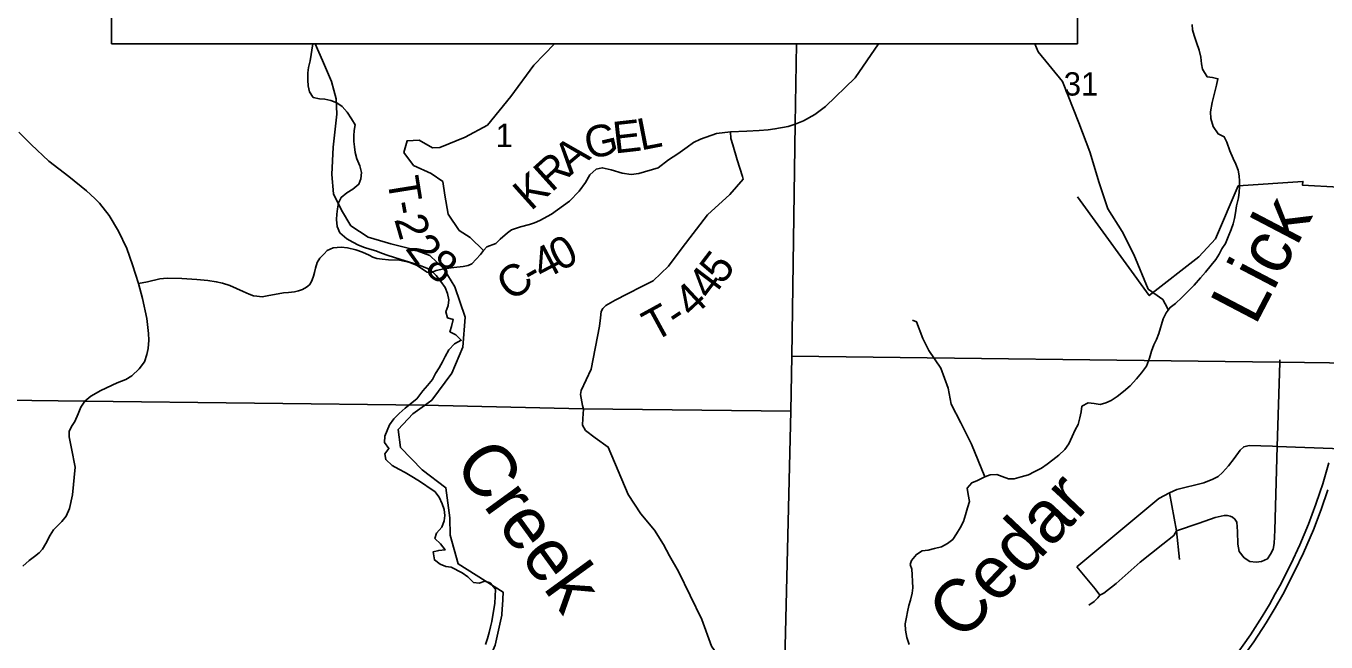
# Model space of a CAD drawing. Extents: x 0 to 34, y 0 to 22.
# Drawn here: x 3.211 to 5.55, y 15.265 to 16.371 of the extents above; entities that cross this region are included whole.
import ezdxf

# ---------------------------------------------------------------- set-up
doc = ezdxf.new("R2010")
doc.units = 0
for name, color, linetype in [('GM_X_Corporation', 7, 'Continuous'), ('GM_X_County_Road', 7, 'Continuous'), ('GM_X_County_Road_Text', 7, 'Continuous'), ('GM_X_Minor_River', 7, 'Continuous'), ('GM_X_Minor_River_Text', 7, 'Continuous'), ('GM_X_Section_Text', 7, 'Continuous'), ('GM_X_State_Route', 7, 'Continuous'), ('GM_X_Township_Road', 7, 'Continuous'), ('GM_X_Township_Road_Text', 7, 'Continuous'), ('GM_X_US_Route', 7, 'Continuous'), ('SH_Text', 7, 'Continuous')]:
    doc.layers.add(name, color=color, linetype=linetype)

msp = doc.modelspace()

# ---------------------------------------------------------------- linework, layer by layer
at = {"layer": 'GM_X_Corporation'}
for points in [[(4.5973, 16.3396), (4.5948, 16.1954), (4.5888, 15.778), (5.4664, 15.7674), (5.6014, 15.7658)], [(5.6386, 16.0784), (5.5079, 16.0853), (5.5084, 16.0923), (5.3919, 16.0842), (5.3514, 15.9891), (5.3213, 15.9569), (5.2318, 15.887), (5.1027, 16.0647)], [(5.6014, 15.7658), (5.4664, 15.7674), (4.5888, 15.778), (4.5873, 15.6794), (4.5738, 15.1325), (4.5685, 14.9157), (4.5617, 14.6817), (4.5616, 14.6767), (4.5614, 14.6695), (4.5505, 14.2449), (4.5507, 14.1138), (4.5503, 14.1), (8.9, 14.1)]]:
    msp.add_lwpolyline(points, dxfattribs=at)
msp.add_lwpolyline([(2.1, 15.7148), (2.1, 14.1), (4.5503, 14.1), (4.5507, 14.1138), (4.5505, 14.2449), (4.5614, 14.6695), (4.5616, 14.6767), (4.5617, 14.6817), (4.5685, 14.9157), (4.5738, 15.1325), (4.5873, 15.6794), (4.2138, 15.6834), (3.9277, 15.6898), (3.3171, 15.6975), (2.4078, 15.7088)], close=True, dxfattribs=at)
at = {"layer": 'GM_X_County_Road'}
for points in [[(4.5465, 16.1848), (4.5584, 16.1867), (4.5821, 16.1911), (4.595, 16.1948), (4.6099, 16.2009), (4.6301, 16.2122), (4.6497, 16.2271), (4.7026, 16.2782), (4.7447, 16.3396)], [(3.4137, 15.9087), (3.4296, 15.9117), (3.4519, 15.9171), (3.4649, 15.9181), (3.4916, 15.9178), (3.5186, 15.9158), (3.5386, 15.9141), (3.5536, 15.912), (3.5646, 15.9093), (3.5778, 15.9052), (3.59, 15.8998), (3.6016, 15.8944), (3.6124, 15.8897), (3.6204, 15.8863), (3.6262, 15.8857), (3.636, 15.885), (3.645, 15.8864), (3.6746, 15.8917), (3.6833, 15.8926), (3.6942, 15.8936), (3.7013, 15.8954), (3.7085, 15.8981), (3.7158, 15.9021), (3.721, 15.9066), (3.7244, 15.9114), (3.7262, 15.9155), (3.7287, 15.9219), (3.7303, 15.9286), (3.7318, 15.9363), (3.7349, 15.9464), (3.7401, 15.9542), (3.7478, 15.9623), (3.7531, 15.968), (3.7641, 15.9731), (3.7782, 15.9743), (3.7896, 15.9727), (3.8043, 15.9693), (3.8163, 15.9653), (3.8283, 15.9596), (3.835, 15.9558), (3.8426, 15.9536), (3.8522, 15.9523), (3.8635, 15.9514), (3.8831, 15.9509), (3.8999, 15.9471), (3.9136, 15.9417), (3.933, 15.9289), (3.9396, 15.928), (3.949, 15.9323), (3.9631, 15.9349), (3.9811, 15.9375), (3.9975, 15.9394), (4.0067, 15.9408), (4.0134, 15.9438), (4.0287, 15.9607), (4.0341, 15.9681), (4.04, 15.9745), (4.0562, 15.9809), (4.0644, 15.9883), (4.0774, 15.9999), (4.0848, 16.005), (4.101, 16.0107), (4.1172, 16.0148), (4.1263, 16.0177), (4.1357, 16.0217), (4.1563, 16.0335), (4.1891, 16.0567), (4.2061, 16.0745), (4.2179, 16.0905), (4.2255, 16.1043), (4.237, 16.1143), (4.248, 16.1169), (4.2637, 16.1132), (4.2836, 16.1072), (4.2998, 16.1049), (4.3137, 16.1062), (4.3486, 16.1166), (4.3673, 16.1307), (4.3836, 16.1418), (4.4005, 16.1538), (4.4122, 16.1622), (4.4245, 16.1679), (4.4532, 16.1781), (4.4788, 16.1813), (4.5082, 16.1826), (4.5299, 16.1838), (4.5465, 16.1848)]]:
    msp.add_lwpolyline(points, dxfattribs=at)
at = {"layer": 'GM_X_Minor_River'}
for points in [[(5.3245, 16.3158), (5.3219, 16.3278), (5.3169, 16.3417), (5.3127, 16.3542), (5.31, 16.3647), (5.3094, 16.3742)], [(3.7272, 16.3396), (3.7223, 16.309), (3.7194, 16.2968), (3.7184, 16.2873), (3.7182, 16.2744), (3.7191, 16.2641), (3.7212, 16.2531), (3.7281, 16.2433), (3.7392, 16.2408), (3.7491, 16.2398), (3.7598, 16.2377), (3.7705, 16.2336), (3.7801, 16.2269), (3.789, 16.2164), (3.7968, 16.2044), (3.8034, 16.1938), (3.8016, 16.1839), (3.801, 16.174), (3.8011, 16.1637), (3.802, 16.1542), (3.8033, 16.144), (3.8065, 16.1326), (3.8116, 16.1202), (3.8148, 16.1084), (3.8134, 16.0966), (3.8098, 16.0871), (3.7989, 16.0782), (3.7883, 16.0716), (3.7781, 16.0634), (3.7733, 16.0539), (3.7716, 16.0428)], [(5.2659, 15.8612), (5.2648, 15.8643), (5.2566, 15.8798), (5.2298, 15.8987), (5.2045, 15.9606), (5.1833, 16.0024), (5.1577, 16.0427), (5.1421, 16.0899), (5.1249, 16.1451), (5.105, 16.1972), (5.0761, 16.272), (5.032, 16.3248), (5.0263, 16.3396)], [(4.8018, 15.4037), (4.804, 15.4108), (4.8131, 15.4218), (4.8232, 15.4282), (4.8342, 15.4296), (4.8459, 15.4327), (4.8583, 15.4357), (4.8688, 15.4414), (4.8784, 15.4489), (4.885, 15.459), (4.8915, 15.4695), (4.8976, 15.4811), (4.9014, 15.493), (4.9052, 15.5056), (4.9086, 15.5172), (4.9063, 15.5296), (4.9041, 15.541), (4.9125, 15.5507), (4.923, 15.5549), (4.9361, 15.561), (4.9459, 15.5651), (4.958, 15.5655), (4.9676, 15.562), (4.9788, 15.5578), (4.9887, 15.5577), (5.0015, 15.5611), (5.0147, 15.565), (5.0252, 15.5703), (5.0379, 15.5771), (5.0483, 15.5839), (5.0587, 15.5918), (5.0691, 15.6002), (5.0802, 15.6104), (5.0875, 15.6205), (5.0935, 15.634), (5.0988, 15.6456), (5.1039, 15.6556), (5.1073, 15.6671), (5.1096, 15.6782), (5.1104, 15.6881), (5.122, 15.6942), (5.1331, 15.693), (5.1438, 15.6911), (5.154, 15.6945), (5.1637, 15.6986), (5.1741, 15.7054), (5.1856, 15.7148), (5.1975, 15.7247), (5.2093, 15.7373), (5.218, 15.7482), (5.2272, 15.7603), (5.2324, 15.7745), (5.2358, 15.7871), (5.2404, 15.7983), (5.245, 15.8083), (5.2489, 15.8187), (5.2568, 15.8452), (5.2622, 15.856), (5.2695, 15.8658), (5.2791, 15.8729), (5.2906, 15.8835), (5.3016, 15.8945), (5.3127, 15.9059), (5.3244, 15.9192), (5.3329, 15.929), (5.3435, 15.9415), (5.3515, 15.9516), (5.3577, 15.9613), (5.3627, 15.971), (5.3689, 15.9807), (5.3742, 15.9926), (5.3795, 16.0057), (5.383, 16.0157), (5.3853, 16.0257), (5.3873, 16.0356), (5.3892, 16.0482), (5.3925, 16.0628), (5.3937, 16.0727), (5.3942, 16.0826), (5.3943, 16.0925), (5.3936, 16.1024), (5.3917, 16.1122), (5.388, 16.1231), (5.3831, 16.1336), (5.377, 16.1471), (5.3715, 16.1629), (5.367, 16.1726), (5.3558, 16.1776), (5.3467, 16.191), (5.3428, 16.2053), (5.3424, 16.2175), (5.3449, 16.2343), (5.3494, 16.2511), (5.3531, 16.2649), (5.3554, 16.2768), (5.3458, 16.2788), (5.3363, 16.28), (5.3275, 16.2938), (5.326, 16.3036), (5.3245, 16.3158)], [(3.7716, 16.0428), (3.7705, 16.0333), (3.7699, 16.0238), (3.7712, 16.0113), (3.7759, 15.9999), (3.7883, 15.9891), (3.7994, 15.9828), (3.8093, 15.9776), (3.8201, 15.9732), (3.8296, 15.9706), (3.8403, 15.9677), (3.8506, 15.9633), (3.8625, 15.9593), (3.8724, 15.956), (3.8858, 15.9517), (3.9072, 15.9451), (3.9183, 15.9415), (3.9294, 15.9374), (3.9389, 15.9334), (3.949, 15.9233), (3.9575, 15.9124), (3.9652, 15.9014), (3.9696, 15.8909), (3.9716, 15.8795), (3.9706, 15.8692), (3.9662, 15.8577), (3.9694, 15.8471), (3.9797, 15.8439), (3.9764, 15.8316), (3.9739, 15.8221), (3.9846, 15.8162), (3.9943, 15.8068), (3.9822, 15.8002), (3.9721, 15.7898), (3.9654, 15.7775), (3.9606, 15.7679), (3.9546, 15.7572), (3.9479, 15.7472), (3.9427, 15.7361), (3.9337, 15.7257), (3.9251, 15.7161), (3.9143, 15.7015), (3.903, 15.6922), (3.8932, 15.6849), (3.8823, 15.6752), (3.8729, 15.6656), (3.8651, 15.6545), (3.861, 15.6445), (3.8566, 15.6342), (3.8564, 15.6232), (3.8641, 15.6123), (3.857, 15.6027), (3.8583, 15.5924), (3.8698, 15.5815), (3.8821, 15.5749), (3.8932, 15.5689), (3.9051, 15.5619), (3.9159, 15.5556), (3.9266, 15.5489), (3.9366, 15.5418), (3.9466, 15.5351), (3.9547, 15.5249), (3.9598, 15.5129), (3.9634, 15.5023), (3.9647, 15.492), (3.9637, 15.4821), (3.9592, 15.471), (3.9495, 15.4602), (3.947, 15.4507), (3.957, 15.441), (3.9651, 15.4301), (3.9537, 15.4291), (3.9439, 15.4267), (3.946, 15.4119), (3.9563, 15.4041), (3.9663, 15.4004), (3.9762, 15.3987), (3.996, 15.3887)], [(4.9361, 15.561), (4.912, 15.6198), (4.8928, 15.6586), (4.8755, 15.6921), (4.8701, 15.7205), (4.857, 15.7568), (4.8352, 15.7884), (4.8247, 15.8098), (4.8135, 15.8397), (4.8063, 15.843)], [(4.8018, 15.4037), (4.8047, 15.3953), (4.8056, 15.3854), (4.8059, 15.3733), (4.8065, 15.3619), (4.8052, 15.352), (4.8024, 15.3397), (4.7992, 15.3298), (4.7971, 15.3187), (4.7954, 15.3092), (4.7926, 15.297), (4.7932, 15.2859), (4.7958, 15.2723), (4.8002, 15.2598)], [(3.996, 15.3887), (4.0058, 15.3813), (4.0162, 15.3715), (4.0264, 15.3704), (4.0367, 15.3735), (4.0462, 15.3706), (4.0558, 15.3596), (4.0555, 15.346), (4.0545, 15.3342), (4.0527, 15.3228), (4.0512, 15.3129), (4.0491, 15.3011), (4.0469, 15.2915), (4.0447, 15.2817), (4.0417, 15.2706), (4.038, 15.2599)]]:
    msp.add_lwpolyline(points, dxfattribs=at)
at = {"layer": 'GM_X_State_Route'}
for points in [[(3.4137, 15.9087), (3.403, 15.9423), (3.3924, 15.9718), (3.3774, 16.0029), (3.3607, 16.0307), (3.3437, 16.0533), (3.3351, 16.0618), (3.3199, 16.0751), (3.288, 16.1009), (3.2525, 16.1288), (3.2208, 16.1586), (3.1981, 16.1808)], [(3.2057, 15.4009), (3.2169, 15.4107), (3.2265, 15.4179), (3.2346, 15.4249), (3.2406, 15.4311), (3.2471, 15.4412), (3.2544, 15.4566), (3.2609, 15.4658), (3.2759, 15.4808), (3.2833, 15.4906), (3.2896, 15.5044), (3.2948, 15.5287), (3.2999, 15.5784), (3.2931, 15.6122), (3.289, 15.6329), (3.289, 15.6429), (3.2928, 15.6518), (3.2988, 15.661), (3.3051, 15.6744), (3.3097, 15.6865), (3.3173, 15.697), (3.3279, 15.7061), (3.3458, 15.7166), (3.3752, 15.73), (3.3906, 15.7361), (3.4016, 15.7431), (3.415, 15.7553), (3.4241, 15.7682), (3.4287, 15.7809), (3.431, 15.7918), (3.4319, 15.8067), (3.4313, 15.819), (3.4287, 15.846), (3.4209, 15.8818), (3.4137, 15.9087)]]:
    msp.add_lwpolyline(points, dxfattribs=at)
at = {"layer": 'GM_X_Township_Road'}
for points in [[(3.9631, 15.9349), (3.938, 15.9593), (3.9082, 15.9701), (3.8678, 15.9798), (3.827, 15.9918), (3.7958, 16.0124), (3.7789, 16.0404), (3.7642, 16.0701), (3.7612, 16.1045), (3.764, 16.1539), (3.7703, 16.2128), (3.7693, 16.2405), (3.7611, 16.2718), (3.7447, 16.3098), (3.7315, 16.3396)], [(3.9646, 16.0674), (3.9609, 16.092), (3.9403, 16.1062), (3.9086, 16.121), (3.891, 16.1439), (3.8968, 16.1652), (3.9188, 16.1662), (3.9428, 16.1525), (3.9557, 16.1534), (4.001, 16.1717), (4.0413, 16.193), (4.0836, 16.2447), (4.1246, 16.3013), (4.162, 16.3396)], [(4.2126, 15.6897), (4.2089, 15.7091), (4.2099, 15.7167), (4.2282, 15.7546), (4.2431, 15.8318), (4.2448, 15.847), (4.246, 15.8583), (4.2489, 15.864), (4.2544, 15.8695), (4.271, 15.879), (4.2936, 15.8901), (4.319, 15.9035), (4.3393, 15.9138), (4.3673, 15.9398), (4.3915, 15.973), (4.4372, 16.0324), (4.4772, 16.0685), (4.5015, 16.0962), (4.5, 16.1013), (4.4907, 16.1308), (4.4827, 16.1577), (4.479, 16.1695), (4.4788, 16.1813)], [(4.0341, 15.9681), (4.0105, 15.9916), (3.9907, 16.0039), (3.9705, 16.0332), (3.9646, 16.0674)], [(4.0681, 15.3252), (4.0683, 15.3294), (4.0694, 15.3542), (3.9885, 15.4047), (3.9742, 15.4564), (3.9735, 15.4879), (3.9667, 15.5416), (3.9239, 15.574), (3.8847, 15.6141), (3.8806, 15.6463), (3.9073, 15.6745), (3.9279, 15.6892), (3.9413, 15.6988), (3.977, 15.7478), (3.9969, 15.7945), (4.0014, 15.8484), (3.9828, 15.9026), (3.9631, 15.9349)], [(5.1232, 15.3304), (5.1328, 15.3374), (5.1396, 15.3441), (5.1433, 15.3488), (5.1503, 15.3522), (5.1722, 15.3699), (5.2159, 15.4079), (5.2566, 15.4402), (5.2764, 15.4559), (5.2807, 15.4643), (5.3215, 15.4779), (5.3505, 15.4881), (5.3666, 15.4918), (5.3727, 15.4919), (5.3773, 15.4907), (5.3819, 15.4889), (5.3861, 15.4853), (5.3896, 15.4799), (5.3908, 15.4632), (5.3914, 15.4403), (5.3937, 15.427), (5.4028, 15.4159), (5.4129, 15.4093), (5.4242, 15.408), (5.4341, 15.4089), (5.4444, 15.4142), (5.4501, 15.4224), (5.4547, 15.4313), (5.4567, 15.4414), (5.4576, 15.4657), (5.4622, 15.6159), (5.4666, 15.7669), (5.4667, 15.7714)], [(4.5502, 15.1611), (4.5496, 15.1619), (4.4934, 15.1962), (4.4711, 15.219), (4.4444, 15.2572), (4.4269, 15.3047), (4.385, 15.3914), (4.3689, 15.4195), (4.3582, 15.4397), (4.3417, 15.4652), (4.3172, 15.495), (4.2948, 15.5298), (4.2586, 15.6149), (4.235, 15.6314), (4.2175, 15.6447), (4.2125, 15.6544), (4.2131, 15.6659), (4.214, 15.6829), (4.2126, 15.6897)], [(5.1019, 15.3994), (5.2489, 15.5226), (5.2684, 15.5327), (5.2816, 15.5388), (5.3304, 15.5508), (5.3465, 15.557), (5.3562, 15.562), (5.364, 15.5688), (5.3747, 15.5809), (5.3846, 15.5943), (5.3955, 15.6095), (5.402, 15.6155), (5.4118, 15.6178), (5.4535, 15.6162)], [(5.4535, 15.6162), (5.4622, 15.6159), (5.5619, 15.6123), (5.5742, 15.6117), (5.6094, 15.6105)], [(5.2865, 15.4125), (5.2807, 15.4643), (5.2684, 15.5327)], [(5.1433, 15.3488), (5.1344, 15.3601), (5.1104, 15.3885), (5.1019, 15.3994)], [(4.1181, 15.1541), (4.112, 15.1562), (4.0597, 15.1614), (4.038, 15.2179), (4.0551, 15.2588), (4.0675, 15.3128), (4.0681, 15.3252)]]:
    msp.add_lwpolyline(points, dxfattribs=at)
at = {"layer": 'GM_X_US_Route'}
for points in [[(5.388, 15.2404), (5.4139, 15.2775), (5.4349, 15.3101), (5.448, 15.332), (5.4587, 15.3508), (5.4666, 15.3654), (5.4866, 15.4046), (5.5026, 15.4393), (5.5182, 15.4762), (5.5317, 15.5124), (5.5389, 15.5331), (5.544, 15.5488), (5.5553, 15.5862)], [(5.389, 15.2214), (5.4201, 15.265), (5.4421, 15.2992), (5.4584, 15.3258), (5.472, 15.35), (5.4934, 15.3911), (5.5092, 15.4249), (5.5273, 15.4662), (5.541, 15.5026), (5.5533, 15.5378)]]:
    msp.add_lwpolyline(points, dxfattribs=at)
at = {"layer": 'SH_Text'}
msp.add_lwpolyline([(3.3651, 16.3396), (5.1027, 16.3396), (5.1027, 17.0396), (3.3651, 17.0396)], close=True, dxfattribs=at)

# ---------------------------------------------------------------- texts
at = {"layer": 'GM_X_County_Road_Text'}
for s, rotation, p in [('G', 12.8797, (4.223, 16.1313)), ('E', 6.4377, (4.2701, 16.1422)), ('L', 10.9737, (4.3172, 16.1477)), ('A', 40.1232, (4.1911, 16.1023)), ('R', 41.9739, (4.1568, 16.0714)), ('K', 41.9823, (4.1196, 16.0379)), ('4', 27.752, (4.1405, 15.9132)), ('0', 27.8832, (4.1716, 15.9296)), ('C', 36.9035, (4.0849, 15.875)), ('-', 29.3799, (4.1206, 15.902))]:
    msp.add_text(s, height=0.0568, rotation=rotation, dxfattribs=at).set_placement(p)
at = {"layer": 'GM_X_Minor_River_Text'}
for s, height, rotation, p in [('Lick', 0.09467, 62.401, (5.4225, 15.8311)), ('Creek', 0.09468, 305.9828, (3.9791, 15.5837)), ('Cedar', 0.09468, 46.5505, (4.8944, 15.2633))]:
    msp.add_text(s, height=height, rotation=rotation, dxfattribs=at).set_placement(p)
at = {"layer": 'GM_X_Section_Text'}
for s, height, p in [('31', 0.04186, (5.0781, 16.2465)), ('1', 0.0419, (4.056, 16.154))]:
    msp.add_text(s, height=height, rotation=0, dxfattribs=at).set_placement(p)
at = {"layer": 'GM_X_Township_Road_Text'}
for s, rotation, p in [('T', 279.1023, (3.8607, 16.0968)), ('-', 280.4116, (3.8676, 16.0535)), ('2', 286.2071, (3.8733, 16.0244)), ('2', 305.8587, (3.8923, 15.9718)), ('8', 323.1255, (3.9259, 15.9302)), ('5', 52.7065, (4.4638, 15.9049)), ('4', 52.8517, (4.4427, 15.877)), ('4', 42.9457, (4.4099, 15.8452)), ('T', 28.6891, (4.3407, 15.8029)), ('-', 33.4929, (4.3824, 15.826))]:
    msp.add_text(s, height=0.0568, rotation=rotation, dxfattribs=at).set_placement(p)

doc.saveas('drawing.dxf')
